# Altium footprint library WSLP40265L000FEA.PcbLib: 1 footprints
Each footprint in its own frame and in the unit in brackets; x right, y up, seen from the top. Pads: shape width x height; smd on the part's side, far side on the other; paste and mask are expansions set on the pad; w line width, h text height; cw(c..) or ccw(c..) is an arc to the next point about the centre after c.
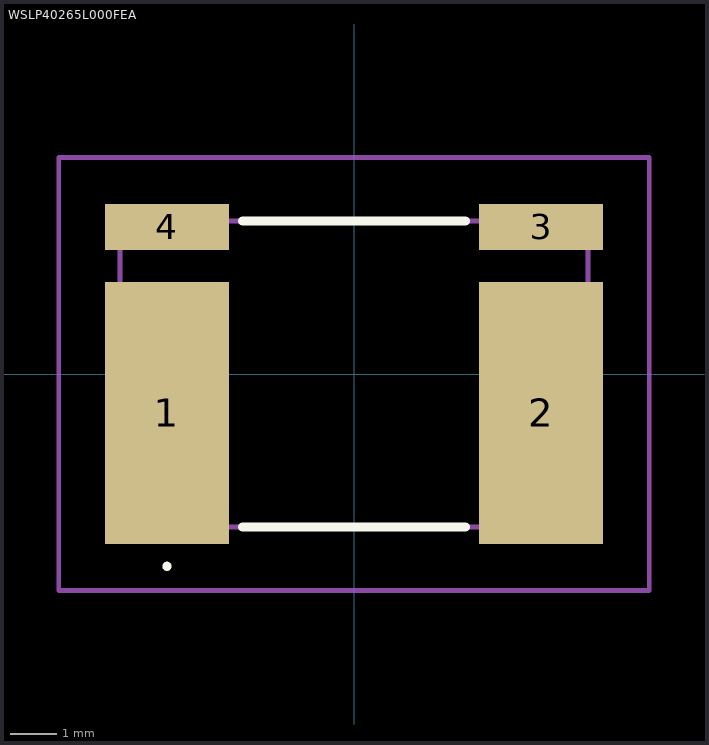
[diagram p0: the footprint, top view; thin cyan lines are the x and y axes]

## WSLP40265L000FEA [mm]
pads (4):
  rect 2.67x5.66 smd: 1(-4.035,-0.84) 2(4.035,-0.84)
  rect 2.67x0.99 smd: 3(4.035,3.175) 4(-4.035,3.175)
Top Overlay:
  lines w0.1: -4.035,-4.2 -4.035,-4.2 ; -4.035,-4.2 ccw(c-4.035,-4.15) -4.035,-4.1 ; -4.035,-4.2 cw(c-4.035,-4.15) -4.035,-4.1 ; -4.035,-4.1 -4.035,-4.1
  lines w0.2: -2.4,-3.3 2.4,-3.3 ; -2.4,3.3 2.4,3.3
Mechanical 15:
  lines w0.1: -5.05,-3.3 5.05,-3.3 5.05,3.3 -5.05,3.3 -5.05,-3.3
Mechanical 20:
  lines w0.1: -6.37,-4.67 6.37,-4.67 6.37,4.67 -6.37,4.67 -6.37,-4.67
